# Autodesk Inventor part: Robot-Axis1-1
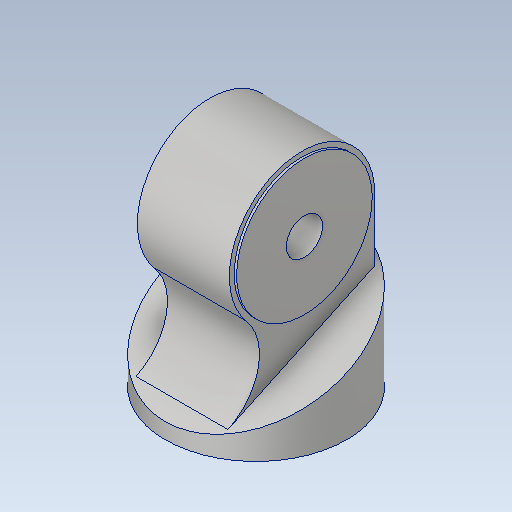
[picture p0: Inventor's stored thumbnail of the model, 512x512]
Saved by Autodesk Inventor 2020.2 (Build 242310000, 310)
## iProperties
Created: 2018-07
Part Number: Robot-Axis1-1
Material: Aluminum 6061
Description: 123456
Document SubType Name: Modeling
Designer: Power User
Mass: 5063.94 g
Surface Area: 1124.06 cm^2
Volume: 1875.53 cm^3
Density: 2.7 g/cm^3
Appearance: Aluminum - Flat
Title: GEAR
Author: Power User
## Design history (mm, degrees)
sketch "Sketch6"
  geometry: C1 r 75 at (0, 0); 1 further point
  constraints: 1 centre point, 1 coincident
  dimensions: "d44" = 150 diameter of C1
extrude "Extrusion5" new body sketch "Sketch6" distance "d45" = 100; taper "d46" = 0 deg
sketch "Sketch7"
  geometry: L1 (0, 75)-(0, -75) reference; L2 (0, 102.879)-(99.808, -111.161); L3 (0, 75)-(100, 75) reference; L4 (0, 102.879)-(-29.654, 102.879); L5 (-29.654, 102.879)-(-29.654, -111.161); L6 (-29.654, -111.161)-(99.808, -111.161); 2 further points
  constraints: 8 end point, 3 point on line, 2 perpendicular, 1 horizontal
  dimensions: "d47" = 25 deg angle of L1 L2; "d49" = 13 distance from line of L1 point (13, 75)
extrude "Extrusion6" sketch "Sketch7" stored distance "d50" = 200; taper "d51" = 0 deg
sketch "Sketch8"
  geometry: L1 (82.946, -75)-(13, 75) reference; L2 (128, -60)-(75.952, -60); L3 (13, 75)-(82.946, -75) reference; L4 (82.946, -75)-(0, -75) reference; L5 (0, -75)-(0, 75) reference; L6 (0, 75)-(13, 75) reference; L7 (0, 75)-(0, -75) reference; L8 (19.444, 61.181)-(75.952, -60); C1 r 56 at (128, 0); C2 r 15 at (128, 0); A1 r 60 centre (128, 0) between (128, -60) and (89.273, 45.828); A2 r 45 centre (60.228, 80.199) between (19.444, 61.181) and (89.273, 45.828); 1 further point
  constraints: 4 centre point, 4 end point, 4 point on circle, 3 tangent, 2 coincident, 2 point on line, 1 collinear, 1 horizontal
  dimensions: "d52" = 75 distance from line of L4 C1.centre; "d53" = 120 diameter of A1; "d54" = 112 diameter of C1; "d55" = 128 distance from line of C1.centre L7; "d56" = 45 radius of A2; "d57" = 30 diameter of C2
  node "Project Cut Edges2"
extrude "Extrusion7" join sketch "Sketch8" stored distance "d58" = 76; taper "d59" = 0 deg
extrude "Extrusion8" join sketch "Sketch8" stored distance "d60" = 80; taper "d61" = 0 deg
body "Solid2"
